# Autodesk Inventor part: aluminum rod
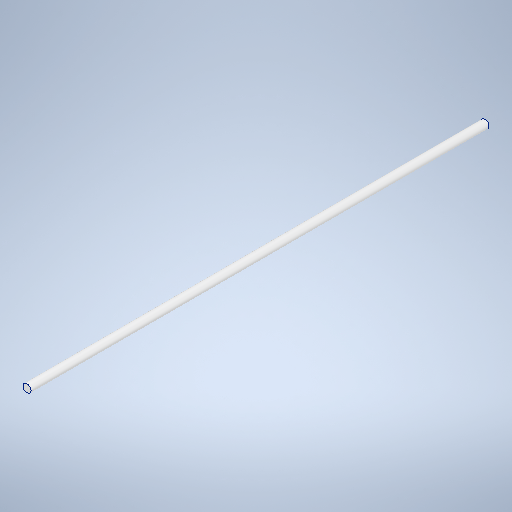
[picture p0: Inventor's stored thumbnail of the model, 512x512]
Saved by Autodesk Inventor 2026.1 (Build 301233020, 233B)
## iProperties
Created: 2026-10
Part Number: aluminum rod
Material: Aluminum 6061
Document SubType Name: Modeling
Designer: hp
Density: 2.7 g/cm^3
Appearance: Aluminum - Flat
Author: hp
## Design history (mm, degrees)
sketch "Sketch1"
  geometry: C1 r 4 at (0, 0); 1 further point
  constraints: 1 centre point, 1 coincident
  dimensions: "d0" = 8 diameter of C1
extrude "Extrusion1" new body sketch "Sketch1" distance "d1" = 450; taper "d2" = 0 deg
body "Solid1"
